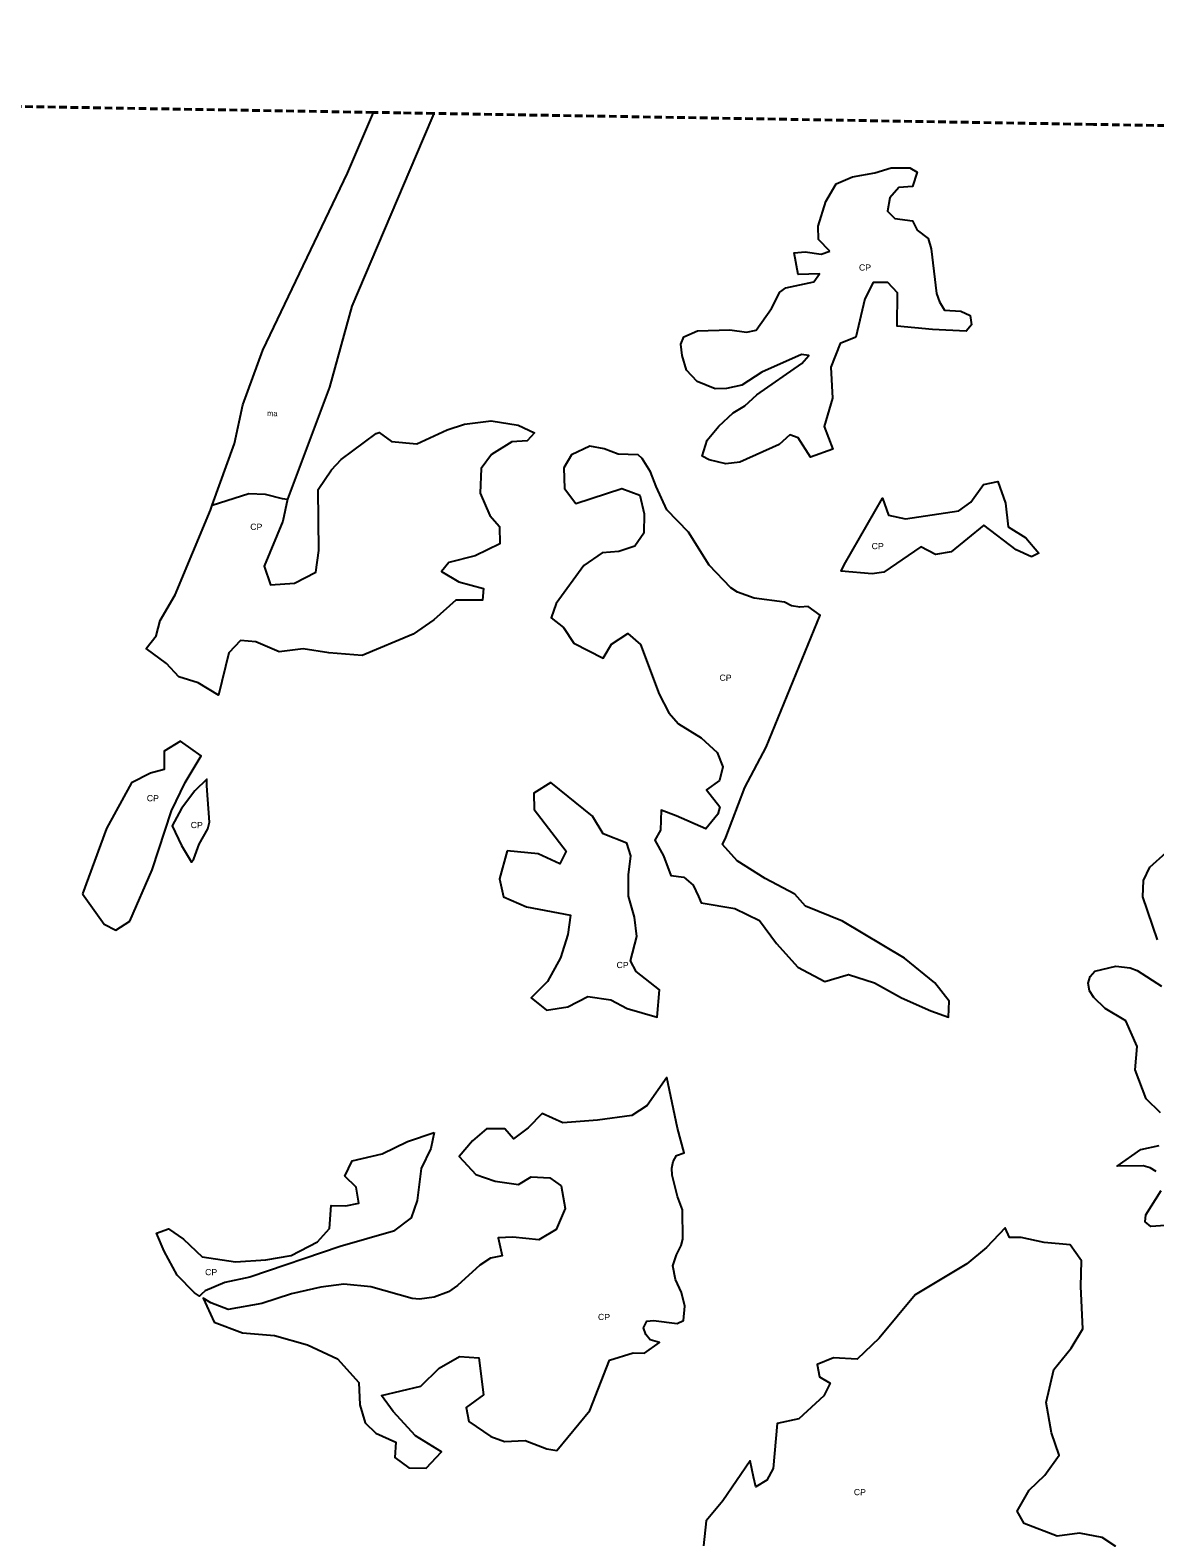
# Model space of a CAD drawing. Extents: x 713589 to 726391, y 7177764 to 7191819.
# Drawn here: x 722384 to 723543, y 7190205 to 7191758 of the extents above; entities that cross this region are included whole.
import ezdxf
from ezdxf.enums import TextEntityAlignment as Align

# ---------------------------------------------------------------- set-up
doc = ezdxf.new("R2010")
doc.units = 0
doc.header["$LTSCALE"] = 2.6
doc.linetypes.add('MEDIUM_DASHED', pattern=[4.5, 3, -1.5])
doc.layers.add('63', color=7, linetype='Continuous', lineweight=25)

msp = doc.modelspace()

# ---------------------------------------------------------------- linework, layer by layer
at = {"layer": '63', "linetype": 'MEDIUM_DASHED', "lineweight": 40}
for points in [[(722737.34, 7191673.64), (722316.94, 7191680.65), (722197.01, 7191682.65), (721409.36, 7191695.54), (720694.41, 7191707.25), (720279.89, 7191714.03), (720035.65, 7191718.03), (719887, 7191720.46), (719596.6, 7191725.22), (719322.11, 7191729.71), (719250.88, 7191730.88), (719190.59, 7191731.86), (718997.41, 7191735.03), (718686.34, 7191740.12), (718003.33, 7191751.3), (717562.67, 7191758.38)], [(722799.61, 7191672.6), (722765.73, 7191673.17), (722737.34, 7191673.64)], [(723830.44, 7191655.4), (723703.9, 7191657.51), (723611.54, 7191659.05), (723479.26, 7191661.26), (722799.61, 7191672.6)]]:
    msp.add_lwpolyline(points, dxfattribs=at)
at = {"layer": '63'}
for points in [[(722571.38, 7191269.07), (722594.16, 7191332.52), (722602.94, 7191372.36), (722623.47, 7191428.6), (722710.74, 7191611.02), (722737.34, 7191673.64)], [(722799.61, 7191672.6), (722788.53, 7191646.58), (722715.06, 7191474.15), (722692.02, 7191390.62), (722648.9, 7191275.25)], [(722648.9, 7191275.25), (722643.94, 7191252.52), (722624.93, 7191205.99), (722631.37, 7191186.77), (722656.05, 7191188.74), (722678.02, 7191199.97), (722681.19, 7191222.24), (722680.36, 7191285.07), (722694.09, 7191305.4), (722704.04, 7191315.93), (722740.35, 7191342.64), (722743.39, 7191343.82), (722755.94, 7191334.71), (722781.97, 7191332.22), (722813.2, 7191346.51), (722831.39, 7191352.27), (722858.81, 7191355.94), (722886.55, 7191351.39), (722903.32, 7191343.45), (722895.75, 7191335.25), (722879.98, 7191334.28), (722859.03, 7191320.99), (722848.36, 7191306.63), (722847.24, 7191281.28), (722857.44, 7191258.29), (722867.34, 7191246.94), (722867.62, 7191229.12), (722842.22, 7191216.88), (722815.12, 7191209.77), (722807.55, 7191200.55), (722825.34, 7191189.86), (722850.67, 7191182.92), (722849.94, 7191170.93), (722822.19, 7191171.03), (722799.5, 7191150.89), (722778.2, 7191135.89), (722725.7, 7191114.14), (722691.44, 7191116.66), (722665.07, 7191120.86), (722640.39, 7191117.87), (722616.09, 7191128.23), (722600.33, 7191129.66), (722588.3, 7191116.68), (722577.76, 7191073.14), (722556.66, 7191085.95), (722536.81, 7191092.19), (722524.18, 7191105.94), (722503.12, 7191121.33), (722513.66, 7191134.41), (722517.82, 7191150.16), (722533.07, 7191176.72), (722569.54, 7191263.94), (722571.38, 7191269.07)], [(722571.38, 7191269.07), (722608.98, 7191281.01), (722625.88, 7191280.12), (722643.32, 7191275.72), (722648.9, 7191275.25)], [(723545.31, 7190821.08), (723530.2, 7190865.55), (723530.97, 7190882.22), (723537.47, 7190896.04), (723554.12, 7190910.99)], [(723548.39, 7190642.76), (723533.71, 7190657.21), (723522.16, 7190687.06), (723524.3, 7190711.04), (723512.72, 7190737.57), (723491.41, 7190750.47), (723479.52, 7190761.58), (723475.36, 7190768.41), (723473.75, 7190776.36), (723475.84, 7190783.31), (723480.55, 7190788.74), (723502.49, 7190793.91), (723517.24, 7190792.22), (723524.41, 7190789.42), (723549.53, 7190773.35)], [(723543.96, 7190582.46), (723537.72, 7190586.29), (723530.49, 7190588.13), (723503.87, 7190587.9), (723528.04, 7190605.14), (723546.9, 7190609.19)], [(723553.58, 7190526.86), (723538.47, 7190525.68), (723532.51, 7190530.59), (723533.14, 7190537.85), (723549.22, 7190562.81)], [(723502.28, 7190196.09), (723488.26, 7190205.39), (723464.98, 7190209.58), (723442.01, 7190206.58), (723407.79, 7190219.72), (723400.64, 7190232.42), (723413.05, 7190253.97), (723429.21, 7190269.33), (723444.01, 7190290.18), (723436.21, 7190313.17), (723430.5, 7190344.37), (723438.5, 7190378.27), (723456.39, 7190400.48), (723468.46, 7190420.31), (723466.21, 7190463.84), (723466.99, 7190490.22), (723455.4, 7190506.71), (723428.33, 7190509.2), (723404.71, 7190514.42), (723392.71, 7190514.47), (723388.29, 7190524.42), (723369.03, 7190503.93), (723348.76, 7190487.21), (723295.53, 7190455.18), (723258.37, 7190410.77), (723235.68, 7190388.91), (723211.35, 7190390.37), (723194.54, 7190383.58), (723196.89, 7190370.89), (723207.83, 7190364.34), (723201.62, 7190351.34), (723175.84, 7190327.44), (723153.55, 7190322.72), (723149.27, 7190276.48), (723142.72, 7190264.51), (723131.45, 7190257.63), (723129.01, 7190267.86), (723125.51, 7190284.33), (723097.53, 7190243.15), (723080.32, 7190222.3), (723077.49, 7190196.61)]]:
    msp.add_lwpolyline(points, dxfattribs=at)
for points in [[(723207.53, 7191530.78), (723195.81, 7191542.58), (723195.56, 7191556.43), (723203.66, 7191581.94), (723214.04, 7191599.99), (723230.97, 7191607.32), (723253.88, 7191611.41), (723270.74, 7191616.6), (723290.04, 7191616.44), (723297.74, 7191612.11), (723292.72, 7191597.23), (723278.58, 7191596.3), (723269.42, 7191585.7), (723267.04, 7191571.88), (723274.62, 7191564.35), (723292.91, 7191562.07), (723297.8, 7191552.43), (723309.06, 7191543.76), (723312.17, 7191533.06), (723317.49, 7191487.15), (723320.74, 7191478.58), (723325.73, 7191470), (723342.62, 7191468.72), (723352.24, 7191464.34), (723353.64, 7191454.73), (723348.05, 7191448.4), (723313.34, 7191449.9), (723277, 7191453.53), (723277.52, 7191487.62), (723267.41, 7191498.36), (723252.45, 7191498.5), (723243.8, 7191481.54), (723234.52, 7191442.13), (723218.45, 7191435.52), (723208.77, 7191411.22), (723210.54, 7191379.33), (723201.65, 7191350.01), (723210.78, 7191326.53), (723187.87, 7191318.52), (723175.15, 7191338.4), (723166.51, 7191341.41), (723155.3, 7191331.47), (723114.86, 7191313.32), (723100.62, 7191311.65), (723083.3, 7191315.8), (723076.11, 7191319.43), (723081.27, 7191335.86), (723093.33, 7191350.39), (723108.19, 7191364.02), (723120, 7191371.35), (723132.54, 7191382.76), (723178.97, 7191415.04), (723185.91, 7191423.13), (723178.63, 7191424.1), (723137.75, 7191406.02), (723117.08, 7191392.56), (723101.11, 7191389.01), (723089.64, 7191388.86), (723070.85, 7191396.41), (723060.04, 7191408.17), (723055.5, 7191423.1), (723054.27, 7191434.82), (723057.18, 7191442.26), (723071.34, 7191448.58), (723104.53, 7191449.44), (723121.91, 7191447.2), (723131.6, 7191449.26), (723147.41, 7191471.52), (723155.97, 7191488.51), (723162.22, 7191492.74), (723191.3, 7191498.94), (723196.9, 7191507.42), (723175.04, 7191506.5), (723170.79, 7191528.9), (723182.18, 7191529.88), (723198.66, 7191527.64)], [(723057.29, 7190885.79), (723066.85, 7190877.53), (723072.22, 7190865.73), (723075.17, 7190859.28), (723109.83, 7190853.33), (723135.14, 7190840.9), (723152.54, 7190817.2), (723174.72, 7190792.79), (723202.34, 7190778.06), (723226.78, 7190785.41), (723253.82, 7190776.75), (723281.53, 7190761.23), (723311.63, 7190747.76), (723329.77, 7190741.53), (723330.52, 7190757.98), (723315.85, 7190776.88), (723284.75, 7190802.34), (723220.81, 7190840.26), (723182.48, 7190855.81), (723171.56, 7190868.19), (723141.12, 7190884.4), (723112.06, 7190902.32), (723097.18, 7190919.36), (723100.45, 7190926.38), (723120.1, 7190977.98), (723141.9, 7191019.7), (723197.6, 7191155.64), (723185.3, 7191164.64), (723176.82, 7191163.78), (723168.2, 7191165.2), (723160.87, 7191169.03), (723129.69, 7191173.13), (723112.63, 7191179.27), (723105.61, 7191183.83), (723083.3, 7191206.96), (723061.93, 7191241.21), (723039.74, 7191264.22), (723028.82, 7191288.26), (723022.95, 7191303.14), (723014.24, 7191316.99), (723010.14, 7191320.87), (722989.59, 7191321.56), (722975.22, 7191327.09), (722960.49, 7191329.88), (722941.62, 7191320.7), (722933.69, 7191307.36), (722934.3, 7191286.11), (722945.89, 7191270.65), (722993.24, 7191286.25), (723011.72, 7191279.33), (723016.45, 7191260.13), (723016.04, 7191240.25), (723006.74, 7191226.58), (722990.27, 7191221.15), (722973.13, 7191219.84), (722954.24, 7191206.89), (722925.66, 7191167.58), (722920.47, 7191152.87), (722933.11, 7191142.88), (722944.02, 7191126.74), (722974.12, 7191111.21), (722982.74, 7191125.58), (722999.57, 7191136.83), (723012.55, 7191125.47), (723031.9, 7191074.35), (723041.77, 7191055.12), (723051.67, 7191043.78), (723074.92, 7191029.31), (723091.66, 7191014.17), (723097.43, 7190999.42), (723093.96, 7190985.38), (723080.56, 7190975.49), (723094.2, 7190957.96), (723092.12, 7190950.43), (723079.83, 7190935.44), (723049.28, 7190948.87), (723033.99, 7190954.62), (723033.13, 7190934.19), (723027.26, 7190923.93), (723036.12, 7190907.8), (723043.93, 7190887.21)], [(723415.39, 7191215.83), (723399.65, 7191223.08), (723366.16, 7191248.21), (723332.82, 7191220.92), (723316.36, 7191218.23), (723301.31, 7191226.17), (723263.19, 7191199.91), (723251.19, 7191198.24), (723219.43, 7191200.87), (723222.55, 7191207.32), (723261.76, 7191276.11), (723268.19, 7191258.49), (723285.65, 7191255), (723340.51, 7191263.04), (723352.87, 7191271.9), (723365.96, 7191290.36), (723380.71, 7191293.39), (723388.51, 7191271.09), (723391.51, 7191246.75), (723409.63, 7191235.38), (723422.94, 7191219.57)], [(722437.63, 7190868.38), (722459.8, 7190837.12), (722472.11, 7190830.91), (722486.54, 7190840.45), (722509.34, 7190893.15), (722529.43, 7190954.07), (722543.58, 7190983.15), (722560.05, 7191010.66), (722538.59, 7191025.66), (722521.76, 7191015.43), (722521.69, 7190996.59), (722507.63, 7190992.87), (722488.07, 7190983), (722462.2, 7190935.8)], [(722552.43, 7190904.5), (722557.78, 7190919.56), (722566.82, 7190935.32), (722568.56, 7190942.47), (722565.61, 7190979.61), (722565.77, 7190986.55), (722553.49, 7190974.55), (722539.72, 7190956.43), (722530.06, 7190938.65), (722539.58, 7190918.4), (722550.05, 7190901.03)], [(722875.08, 7190912.81), (722867.44, 7190884.06), (722871.49, 7190865.54), (722895.1, 7190855.18), (722940.3, 7190846.45), (722937.83, 7190826.58), (722930.21, 7190802.62), (722916.76, 7190778), (722899.91, 7190761.27), (722915.63, 7190748.53), (722937.57, 7190751.88), (722958.17, 7190762.78), (722982.14, 7190759.27), (722998.9, 7190750.3), (723029.61, 7190741.55), (723032.12, 7190769.72), (723007.94, 7190788.3), (723002.16, 7190799.29), (723008.75, 7190824.62), (723006.43, 7190844.51), (723000.33, 7190866.12), (723000.07, 7190888.05), (723002.53, 7190907.57), (722998.47, 7190920.61), (722974.17, 7190930.29), (722963.27, 7190948.49), (722920.22, 7190983.25), (722902.7, 7190972.34), (722902.98, 7190955.21), (722936.07, 7190912.6), (722929.52, 7190899.26), (722907.28, 7190909.62)], [(722740.03, 7190312.93), (722760.55, 7190303.61), (722759.47, 7190287.85), (722773.82, 7190277.18), (722791.64, 7190276.77), (722807.46, 7190293.51), (722780.79, 7190310.05), (722757.58, 7190335.14), (722745.64, 7190351.63), (722786.11, 7190361.09), (722805.02, 7190379.87), (722825.97, 7190391.79), (722845.84, 7190390.35), (722850.84, 7190352.29), (722832.98, 7190339.33), (722835.67, 7190324.93), (722858.23, 7190309.43), (722872.61, 7190304.24), (722893.86, 7190305.2), (722916.1, 7190296.55), (722926.37, 7190294.8), (722960.44, 7190336.15), (722980.5, 7190388.16), (723004.85, 7190395.62), (723016.85, 7190395.23), (723032.12, 7190406.35), (723022.68, 7190408.8), (723018.08, 7190414.29), (723015.76, 7190421.46), (723019.04, 7190428.21), (723026.1, 7190428.79), (723050.31, 7190425.9), (723057.03, 7190428.91), (723058.19, 7190443.48), (723054.71, 7190457.84), (723048.5, 7190471.18), (723046.03, 7190485.26), (723049.74, 7190496.52), (723054.35, 7190505.99), (723056.21, 7190512.77), (723055.99, 7190542.86), (723050.84, 7190556.78), (723045.19, 7190578.64), (723044.86, 7190585.85), (723046.28, 7190592.78), (723049.78, 7190598.87), (723057.44, 7190601.52), (723050.86, 7190627.16), (723039.81, 7190679.31), (723019.45, 7190650.51), (723003.65, 7190639.94), (722968.34, 7190635.27), (722932.7, 7190632.65), (722911.14, 7190641.98), (722896.7, 7190627.3), (722881.58, 7190616.04), (722872.71, 7190626.35), (722853.86, 7190626.42), (722839.43, 7190614.13), (722825.66, 7190597.73), (722843.07, 7190579.17), (722862.92, 7190572.59), (722886.9, 7190569.08), (722899.95, 7190576.91), (722919.13, 7190575.82), (722930.75, 7190567.55), (722934.79, 7190544.24), (722925.8, 7190522.68), (722907.94, 7190512.12), (722880.88, 7190514.61), (722865.8, 7190513.98), (722870.12, 7190495.66), (722857.99, 7190492.94), (722847.02, 7190485.92), (722824.1, 7190464.86), (722814.84, 7190458.34), (722800.05, 7190452.99), (722784.96, 7190450.98), (722777.29, 7190451.56), (722734.86, 7190463.46), (722706.92, 7190466.28), (722683.25, 7190463.14), (722653.01, 7190456.23), (722622.31, 7190446.5), (722587.74, 7190440.22), (722570, 7190447.19), (722562.12, 7190451.82), (722573.2, 7190427.28), (722602.63, 7190416.21), (722635.52, 7190413.36), (722669.41, 7190403.64), (722700.54, 7190389.49), (722722.39, 7190365.08), (722723.34, 7190342.12), (722728.75, 7190323.59)], [(722800.05, 7190622.49), (722796.56, 7190606.06), (722786.55, 7190585.53), (722782.33, 7190552.65), (722776.44, 7190534.51), (722758.23, 7190520.87), (722703, 7190504.96), (722610.03, 7190473.41), (722584.31, 7190468.02), (722564.06, 7190459.52), (722560.27, 7190455.92), (722558.31, 7190454.06), (722552.89, 7190457.24), (722535.3, 7190475.61), (722521.61, 7190500.17), (722513.93, 7190518.83), (722526.25, 7190523.39), (722541.63, 7190512.72), (722560.76, 7190494.49), (722595.35, 7190489.23), (722626.54, 7190491.52), (722652.6, 7190495.88), (722679.72, 7190509.83), (722692.1, 7190523.5), (722693.9, 7190547.48), (722708.98, 7190547.08), (722722.35, 7190549.78), (722719.67, 7190566.23), (722708.06, 7190577.58), (722715.65, 7190593.32), (722746.52, 7190600.75), (722772.6, 7190613.34)]]:
    msp.add_lwpolyline(points, close=True, dxfattribs=at)

# ---------------------------------------------------------------- texts
at = {"layer": '63', "width": 1.05}
for p in [(723243.85, 7191510.62), (722616.66, 7191243.45), (723256.92, 7191223.55), (723100.12, 7191087.95), (722510.07, 7190963.8), (722555.31, 7190936.15), (722994.07, 7190791.92), (722570.13, 7190475.5), (722974.92, 7190429.27), (723238.56, 7190248.84)]:
    msp.add_text('CP', height=6.4, rotation=359.062, dxfattribs=at).set_placement(p, align=Align.CENTER)
at = {"layer": '63'}
msp.add_text('ma', height=5.82, rotation=359.062, dxfattribs=at).set_placement((722633.12, 7191360.62), align=Align.CENTER)

doc.saveas('drawing.dxf')
